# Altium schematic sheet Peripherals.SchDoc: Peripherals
size A4; Date: Not used; ApprovedBy: Not used; CheckedBy: Not used; Author: Not used; CompanyName: STMicroelectronics; DrawnBy: Not used; Engineer: Not used; Organization: Not used; Address1: Not used; Address2: Not used; Address3: Not used; Address4: Not used; DocumentNumber: Not used; Revision: Not used; SheetNumber: 14; SheetTotal: 23
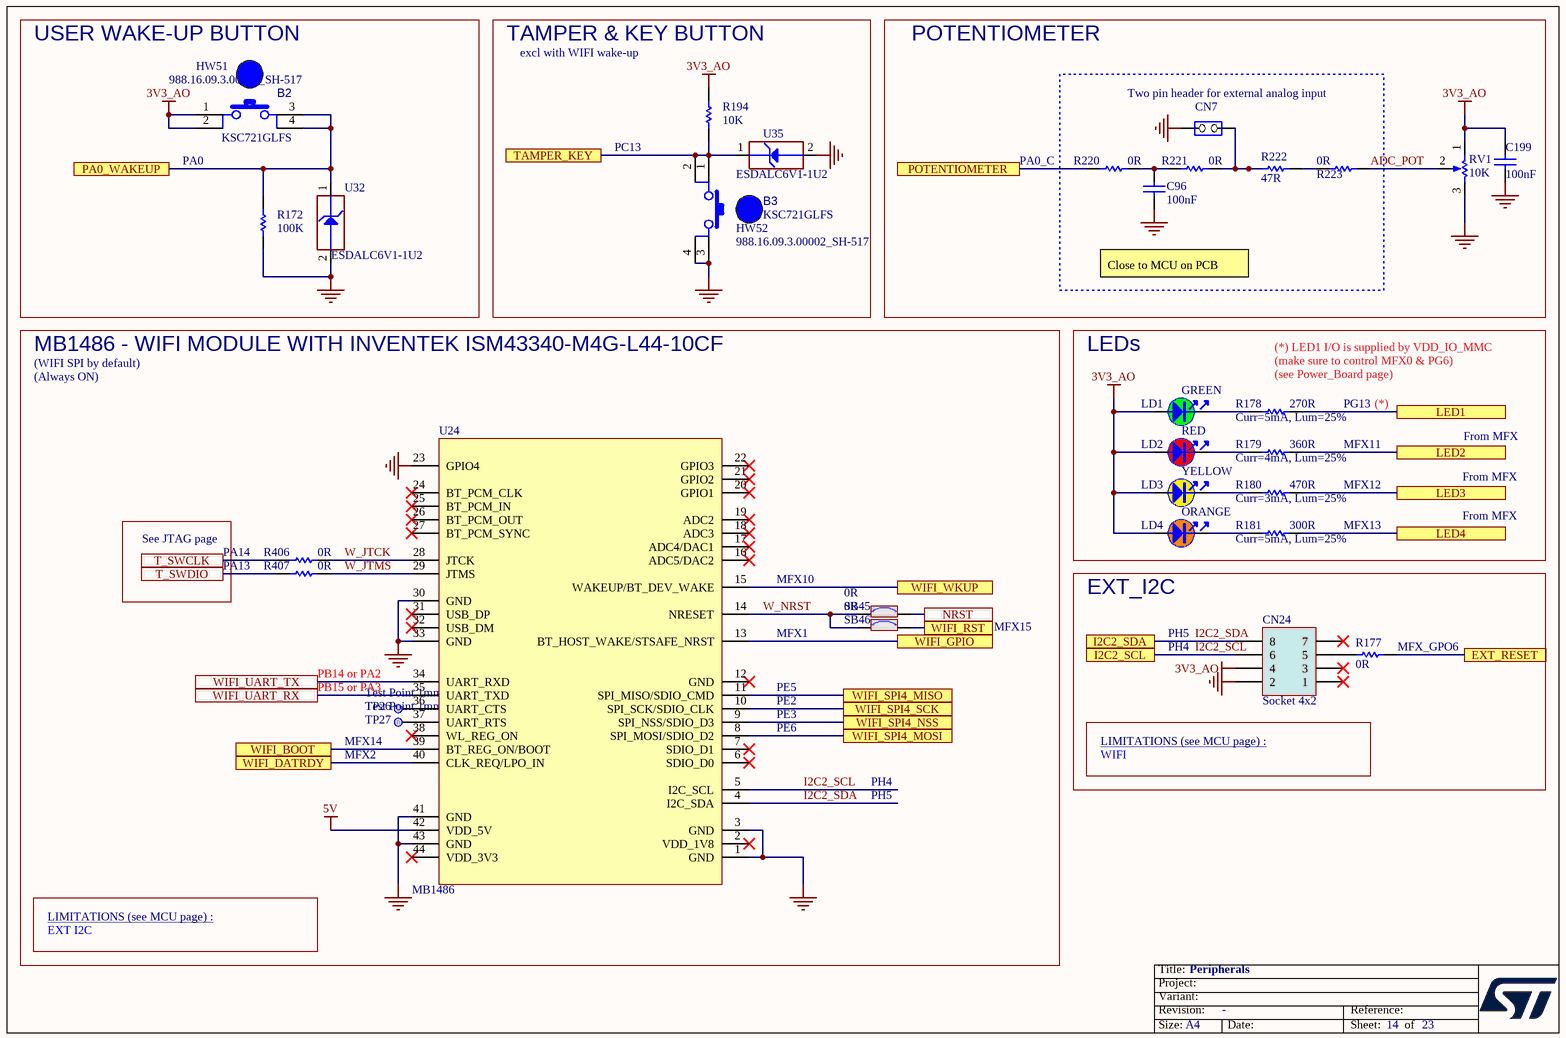
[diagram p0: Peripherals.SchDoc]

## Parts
B2  value KSC721GLFS  [SWI_C&K_KSC721GLFS_BLUE]  (hidden comment: SW_BLUE_KSC721GLFS)
B3  value KSC721GLFS  [SWI_C&K_KSC721GLFS_BLUE]  (hidden comment: SW_BLUE_KSC721GLFS)
C96  value 100nF  [C0603]  (hidden comment: Capacitor)
C199  value 100nF  [C0402]  (hidden comment: Capacitor)
CN7  Jumper_Header 2x1  [CON_SAMTEC_TSW-102-07-G-S]  (value not drawn)
CN24  Socket 4x2  [CON_SAMTEC_SSM-104-L-DH]
HW51  value 988.16.09.3.00002_SH-517  (hidden comment: BUTTON_HAT_BLUE)  (mechanical)
HW52  value 988.16.09.3.00002_SH-517  (hidden comment: BUTTON_HAT_BLUE)  (mechanical)
LD1  value GREEN  [LED_0603_OSRAM_LG-Q396-PS-35_GREEN_1A2K_H0P4]  (hidden comment: LED_green)
LD2  value RED  [LED_0603_VISHAY_VLMS1300-GS08_RED_1A2K_H0P8]  (hidden comment: LED_red)
LD3  value YELLOW  [LED_0603_OSRAM_LY-Q396-P1Q2-36_YELLOW_1A2K_H0P4]  (hidden comment: LED_yellow)
LD4  value ORANGE  [LED_0603_OSRAM_LO-Q976-PS-25_ORANGE_1A2K_H0P8]  (hidden comment: LED_orange)
R172  value 100K  [R0402]  (hidden comment: Resistor)
R177  value 0R  [R0402]  (hidden comment: Resistor)
R178  value 270R  [R0402]  (hidden comment: Resistor)
R179  value 360R  [R0402]  (hidden comment: Resistor)
R180  value 470R  [R0402]  (hidden comment: Resistor)
R181  value 300R  [R0402]  (hidden comment: Resistor)
R194  value 10K  [R0402]  (hidden comment: Resistor)
R220  value 0R  [R0603]  (hidden comment: Resistor)
R221  value 0R  [R0603]  (hidden comment: Resistor)
R222  value 47R  [R0603]  (hidden comment: Resistor)
R223  value 0R  [R0603]  (hidden comment: Resistor)
R406  value 0R  [R0402]  (hidden comment: Resistor)
R407  value 0R  [R0402]  (hidden comment: Resistor)
RV1  value 10K  [POT_BOURNS_3386P]  (hidden comment: POTENTIOMETER)
SB45  value 0R  [SOLDER-BRIDGE_R0603-0R]  (hidden comment: SB_ON)
SB46  value 0R  [SOLDER-BRIDGE_R0603-0R]  (hidden comment: SB_ON)
TP26  value Test Point 1mm  [TP_SMD_1MM]  (hidden comment: Test Point)  (no BOM)
TP27  value Test Point 1mm  [TP_SMD_1MM]  (hidden comment: Test Point)  (no BOM)
U24  value MB1486  [MOD_WIFI_INVENTEK_ISM43362]  (hidden comment: WIFI MODULE INTERPOSER)
U32  value ESDALC6V1-1U2  [ESD_ST0201]  (hidden comment: ESD-TRANSIL)
U35  value ESDALC6V1-1U2  [ESD_ST0201]  (hidden comment: ESD-TRANSIL)

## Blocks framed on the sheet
USER WAKE-UP BUTTON: B2 HW51 R172 U32
TAMPER & KEY BUTTON: B3 HW52 R194 U35
POTENTIOMETER: C199 RV1
Two pin header for external analog input: C96 CN7 R220-R223
MB1486 - WIFI MODULE WITH INVENTEK ISM43340-M4G-L44-10CF: R406 R407 SB45 SB46 TP26 TP27 U24
LEDs: LD1-LD4 R178-R181
EXT_I2C: CN24 R177

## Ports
EXT_RESET, I2C2_SCL, I2C2_SDA, LED1, LED2, LED3, LED4, NRST, PA0_WAKEUP, POTENTIOMETER, T_SWCLK, T_SWDIO, TAMPER_KEY, WIFI_BOOT, WIFI_DATRDY, WIFI_GPIO, WIFI_RST, WIFI_SPI4_MISO, WIFI_SPI4_MOSI, WIFI_SPI4_NSS, WIFI_SPI4_SCK, WIFI_UART_RX, WIFI_UART_TX, WIFI_WKUP

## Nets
3V3_AO: B2.1 B2.2 C199.1 CN24.4 LD1.1 LD2.1 LD3.1 LD4.1 R194.2 RV1.1(BOT)
5V: U24.42(VDD_5V)
GND: B3.3 B3.4 C96.2 C199.2 CN7.2(NO) CN24.2 R172.1 RV1.3(TOP) U24.1(GND) U24.3(GND) U24.23(GPIO4) U24.30(GND) U24.33(GND) U24.41(GND) U24.43(GND) U32.2(GND) U35.2(GND)
ADC_POT: R223.2 RV1.2(TAP)
EXT_RESET: R177.2 ; port EXT_RESET
I2C2_SCL: CN24.6 U24.5(I2C_SCL) ; port I2C2_SCL
I2C2_SDA: CN24.8 U24.4(I2C_SDA) ; port I2C2_SDA
LED1: R178.2 ; port LED1
LED2: R179.2 ; port LED2
LED3: R180.2 ; port LED3
LED4: R181.2 ; port LED4
NRST: SB45.2 ; port NRST
PA0_WAKEUP: B2.3 B2.4 R172.2 U32.1(IO1) ; port PA0_WAKEUP
POTENTIOMETER: R220.2 ; port POTENTIOMETER
T_SWCLK: R406.1 ; port T_SWCLK
T_SWDIO: R407.1 ; port T_SWDIO
TAMPER_KEY: B3.1 B3.2 R194.1 U35.1(IO1) ; port TAMPER_KEY
W_JTCK: R406.2 U24.28(JTCK)
W_JTMS: R407.2 U24.29(JTMS)
W_NRST: SB45.1 SB46.1 U24.14(NRESET)
WIFI_BOOT: U24.39(BT_REG_ON/BOOT) ; port WIFI_BOOT
WIFI_DATRDY: U24.40(CLK_REQ/LPO_IN) ; port WIFI_DATRDY
WIFI_GPIO: U24.13(BT_HOST_WAKE/STSAFE_NRST) ; port WIFI_GPIO
WIFI_RST: SB46.2 ; port WIFI_RST
WIFI_SPI4_MISO: U24.11(SPI_MISO/SDIO_CMD) ; port WIFI_SPI4_MISO
WIFI_SPI4_MOSI: U24.8(SPI_MOSI/SDIO_D2) ; port WIFI_SPI4_MOSI
WIFI_SPI4_NSS: U24.9(SPI_NSS/SDIO_D3) ; port WIFI_SPI4_NSS
WIFI_SPI4_SCK: U24.10(SPI_SCK/SDIO_CLK) ; port WIFI_SPI4_SCK
WIFI_UART_RX: U24.35(UART_TXD) ; port WIFI_UART_RX
WIFI_UART_TX: U24.34(UART_RXD) ; port WIFI_UART_TX
WIFI_WKUP: U24.15(WAKEUP/BT_DEV_WAKE) ; port WIFI_WKUP
NetC96_1: C96.1 R220.1 R221.1
NetCN7_1: CN7.1(COMMON) R221.2 R222.1
NetCN24_5: CN24.5 R177.1
NetLD1_2: LD1.2 R178.1
NetLD2_2: LD2.2 R179.1
NetLD3_2: LD3.2 R180.1
NetLD4_2: LD4.2 R181.1
NetR222_2: R222.2 R223.1
NetTP26_1: TP26.1 U24.36(UART_CTS)
NetTP27_1: TP27.1 U24.37(UART_RTS)

Not connected (* = marked no-connect by the designer): CN24 1* 3* 7*; U24 2(VDD_1V8)* 6(SDIO_D0)* 7(SDIO_D1)* 12(GND)* 16(ADC5/DAC2)* 17(ADC4/DAC1)* 18(ADC3)* 19(ADC2)* 20(GPIO1)* 21(GPIO2)* 22(GPIO3)* 24(BT_PCM_CLK)* 25(BT_PCM_IN)* 26(BT_PCM_OUT)* 27(BT_PCM_SYNC)* 31(USB_DP)* 32(USB_DM)* 38(WL_REG_ON)* 44(VDD_3V3)*

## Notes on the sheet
- excl with WIFI wake-up
- (near B2) PA0
- PC13
- (near R220) PA0_C
- Close to MCU on PCB
- (WIFI SPI by default)
- (Always ON)
- (near R178) (*) LED1 I/O is supplied by VDD_IO_MMC
  (make sure to control MFX0 & PG6)
  (see Power_Board page)
- (near R178) Curr=5mA, Lum=25%
- PG13
- MFX11
- (*)
- From MFX
- (near R179) Curr=4mA, Lum=25%
- (near R180) Curr=3mA, Lum=25%
- MFX12
- See JTAG page
- PA13
- PA14
- MFX10
- (near R181) Curr=5mA, Lum=25%
- MFX13
- MFX1
- MFX15
- PH5
- PH4
- (near R177) MFX_GPO6
- PB14 or PA2
- PB15 or PA3
- PE5
- PE3
- PE2
- MFX14
- MFX2
- PE6
- LIMITATIONS (see MCU page) :
- WIFI
- EXT I2C

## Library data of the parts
B2 B3 = MCD-00176: Switch HW BLUE High4.3mm 2.25 Newtons; Manufacturer: C&K; Part_Type: Misc; Part_Preference: Recommended; Provided_By: SUBCO; Component_Country_Of_Origin: France; ID: 2693; Order_Code_RS: 894-9152; ShowFields: YES
C96 = MCD-02119: Capacitor, MLCC, 100nF, 6V3, X5R, 10%, 0603, T=0,8mm; Manufacturer: KEMET; Manufacturer_Part_Number: C0603C104K9PACTU; Part_Preference: Recommended; ECCN_EU: NEC; ECCN_US: EAR99; Component_Country_Of_Origin: Mexico; ID: 4219; ShowFields: YES
C199 = MCD-00006: Capacitor, MLCC, 100nF, 16V, X7R, 10%, 0402, T=0.5mm; Manufacturer_Part_Number: CC0402KRX7R7BB104; Manufacturer: YAGEO; Alternate_Manufacturer_Part_Number: GCM155R71C104KA55D; Alternate_Manufacturer: MURATA; Part_Preference: Recommended; Partial_Alternate_Internal_Part_Number: MCD-03299; Provided_By: SUBCO; ECCN_US: EAR99; ECCN_EU: NEC; Component_Country_Of_Origin: China; ID: 2474; Order_Code_RS: 9402047; ShowFields: YES
CN7 = MCD-00045: Header, 2x1, 2,54mm, VR, TH, Height 5.84mm/2.54mm; Manufacturer_Part_Number: TSW-102-07-G-S; Manufacturer: SAMTEC; Part_Type: Connector; Alternate_Manufacturer_Part_Number: 313102S111116;313102S111116; Alternate_Manufacturer: JIUBABA; LIANYI; Full_Alternate_Internal_Part_Number: MCD-02390; Part_Preference: Recommended; Partial_Alternate_Internal_Part_Number: MCD-02957, MCD-03720; Provided_By: SUBCO; Component_Country_Of_Origin: China, Costa Rica, Malaysia, USA, Vietnam; ID: 2545; Order_Code_RS: 2505044; ShowFields: YES
CN24 = MCD-00131: Socket, 4x2, 2.54mm, RA, SMT, Height 5.72mm; Manufacturer_Part_Number: SSM-104-L-DH; Manufacturer: SAMTEC; Part_Type: Connector; Alternate_Manufacturer_Part_Number: F206A-2x04MGF-LA; Alternate_Manufacturer: JIUBABA; Part_Preference: Recommended; Provided_By: SUBCO; ECCN_US: EAR99; ECCN_EU: NEC; Component_Country_Of_Origin: China, Costa Rica, Malaysia, USA, Vietnam; ID: 2740; Order_Code_RS: 198-1510; ShowFields: YES
HW51 HW52 = MCD-00634: Blue Hat for switch TD0341X-G01-BLU; Part_Type: Mechanical; Manufacturer: JIUBABA; Part_Preference: Alternate; Provided_By: SUBCO; Alternate_EMS: A; Component_Country_Of_Origin: Unknown; ID: 3112; ShowFields: YES
LD1 = MCD-00588: LED Green, 0603 SMD, Forward Voltage Typ=2V, Max=2.5V; Part_Type: Display; Manufacturer_Part_Number: LG Q396-PS-35; Manufacturer: OSRAM OPTO SEMICONDUCTORS; Alternate_Manufacturer_Part_Number: VLMTG1300-GS08; Alternate_Manufacturer: VISHAY SEMICONDUCTOR OPTO DIVISION; Part_Preference: Recommended; Partial_Alternate_Internal_Part_Number: MCD-02400, MCD-03155; Provided_By: SUBCO; Component_Country_Of_Origin: Unknown; ID: 3155; ShowFields: YES
LD2 = MCD-00587: LED Red, 0603 SMD, 2V Forward Voltage; Part_Type: Display; Manufacturer_Part_Number: VLMS1300-GS08; Manufacturer: VISHAY; Alternate_Manufacturer_Part_Number: LS Q976-NR-1; Alternate_Manufacturer: OSRAM OPTO SEMICONDUCTORS; Full_Alternate_Internal_Part_Number: MCD-02401; Part_Preference: Recommended; Provided_By: SUBCO; Component_Country_Of_Origin: China; ID: 3154; ShowFields: YES
LD3 = MCD-01061: LED Yellow, 0603 SMD, Forward Voltage min=1.7V, Typ=2V, Max=2.3V; Part_Type: Display; Manufacturer_Part_Number: LY Q396-P1Q2-36; Manufacturer: OSRAM OPTO SEMICONDUCTORS; Part_Preference: Recommended; Provided_By: SUBCO; Component_Country_Of_Origin: Unknown; ID: 3242; ShowFields: YES
LD4 = MCD-00590: LED Orange, 0603 SMD, Forward Voltage Min=1.6V, Max=2.4V; Part_Type: Display; Manufacturer_Part_Number: LO Q976-PS-25; Manufacturer: OSRAM OPTO SEMICONDUCTORS; Alternate_Manufacturer_Part_Number: VLMO1300-GS08; Alternate_Manufacturer: VISHAY SEMICONDUCTOR OPTO DIVISION; Part_Preference: Recommended; Provided_By: SUBCO; Component_Country_Of_Origin: Unknown; ID: 3156; ShowFields: YES
R172 = MCD-00059: Resistor,100K,0402,1%,1/16W; Manufacturer_Part_Number: RC0402FR-07100KL; Manufacturer: YAGEO; Alternate_Manufacturer_Part_Number: RT0402FRE07100KL; Part_Preference: Recommended; Partial_Alternate_Internal_Part_Number: MCD-03301; Provided_By: SUBCO; ECCN_US: EAR99; ECCN_EU: NEC; Component_Country_Of_Origin: China; ID: 2533; Order_Code_RS: 2421891; ShowFields: YES
R177 R406 R407 = MCD-00052: Resistor,0R,0402,5%,1/16W; Manufacturer_Part_Number: RC0402JR-070RL; Manufacturer: YAGEO; Part_Preference: Recommended; Provided_By: SUBCO; ECCN_US: EAR99; ECCN_EU: NEC; Component_Country_Of_Origin: China; ID: 2540; Order_Code_RS: 9232516RL; ShowFields: YES
R178 = MCD-00441: Resistor,270R,0402,1%,1/16W; Manufacturer_Part_Number: RC0402FR-07270RL; Manufacturer: YAGEO; Part_Preference: Recommended; Provided_By: SUBCO; ECCN_US: EAR99; ECCN_EU: NEC; Component_Country_Of_Origin: China; ID: 2838; ShowFields: YES
R179 = MCD-00461: Resistor,360R,0402,1%,1/16W; Manufacturer_Part_Number: RC0402FR-07360RL; Manufacturer: YAGEO; Part_Preference: Recommended; Provided_By: SUBCO; ECCN_US: EAR99; ECCN_EU: NEC; Component_Country_Of_Origin: China; ID: 2816; ShowFields: YES
R180 = MCD-00178: Resistor,470R,0402,1%,1/16W; Manufacturer_Part_Number: RC0402FR-07470RL; Manufacturer: YAGEO; Part_Preference: Recommended; Provided_By: SUBCO; ECCN_US: EAR99; ECCN_EU: NEC; Component_Country_Of_Origin: China; ID: 2689; ShowFields: YES
R181 = MCD-00449: Resistor,300R,0402,1%,1/16W; Manufacturer_Part_Number: RC0402FR-07300RL; Manufacturer: YAGEO; Part_Preference: Recommended; Provided_By: SUBCO; ECCN_US: EAR99; ECCN_EU: NEC; Component_Country_Of_Origin: China; ID: 2832; ShowFields: YES
R194 = MCD-00053: Resistor,10K,0402,1%,1/16W; Manufacturer_Part_Number: RC0402FR-0710KL; Manufacturer: YAGEO; BMS_Part_Number: 9131590; Part_Preference: Recommended; Provided_By: SUBCO; ECCN_US: EAR99; ECCN_EU: NEC; Component_Country_Of_Origin: China; ID: 2539; Order_Code_RS: 9239359; ShowFields: YES
R220 R221 R223 = MCD-00056: Resistor,0R,0603,5%,1/10W; Manufacturer_Part_Number: RC0603JR-070RL; Manufacturer: YAGEO; Part_Preference: Recommended; Provided_By: SUBCO; ECCN_US: EAR99; ECCN_EU: NEC; Component_Country_Of_Origin: China; ID: 2536; Order_Code_RS: 9233130RL; ShowFields: YES
R222 = MCD-00482: Resistor,47R,0603,1%,1/10W; Manufacturer_Part_Number: RC0603FR-0747RL; Manufacturer: YAGEO; Part_Preference: Recommended; Provided_By: SUBCO; ECCN_US: EAR99; ECCN_EU: NEC; Component_Country_Of_Origin: China; ID: 2795; ShowFields: YES
RV1 = MCD-00575: TRIMMER 10K OHM 0.5W PC PIN; Part_Type: Resistor; Manufacturer_Part_Number: 3386P-1-103; Manufacturer: BOURNS; BMS_Part_Number: 9036661; Part_Preference: Recommended; Provided_By: SUBCO; ECCN_US: EAR99; ECCN_EU: NEC; Component_Country_Of_Origin: Costa Rica; ID: 3166; Order_Code_RS: 522-2693; ShowFields: YES
SB45 SB46 = MCD-00071: Solder Bridge ON; Part_Type: Resistor; Manufacturer_Part_Number: RC0603JR-070RL; Manufacturer: YAGEO; Manufacturer_HQ_COO: Unknown; Part_Preference: Recommended; Provided_By: SUBCO; Component_Country_Of_Origin: China; ID: 2521; Order_Code_RS: 199-5647; ShowFields: YES
TP26 TP27 = MCD-00074: Test Point 1mm; Part_Type: Misc; Part_Preference: Recommended; Component_Country_Of_Origin: Unknown; ID: 2518; ShowFields: YES
U24 = MCD-01999: 44 pins Interposer for WIFI module (MB1486 module is with INVENTEK ISM43340-M4G-L44-10CF); Part_Type: Misc; Manufacturer_Part_Number: MB1486 - WIFI MODULE WITH INVENTEK ISM43340-M4G-L44-10CF; Manufacturer: STMICROELECTRONICS; Manufacturer_HQ_COO: EU; Part_Preference: Recommended; ECCN_US: 5A002A4; Provided_By: SUBCO with ST control; Component_Country_Of_Origin: Unknown; ID: 4099; ShowFields: YES
U32 U35 = MCD-00170: ESD protection 6V1; Part_Type: Diode; Manufacturer: STMICROELECTRONICS; BMS_Part_Number: 9151132; Manufacturer_HQ_COO: EU; Part_Preference: Recommended; Provided_By: SUBCO with ST control; ECCN_US: EAR99; ECCN_EU: NEC; Component_Country_Of_Origin: China; ID: 2696; Order_Code_RS: 795-8404; ShowFields: YES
